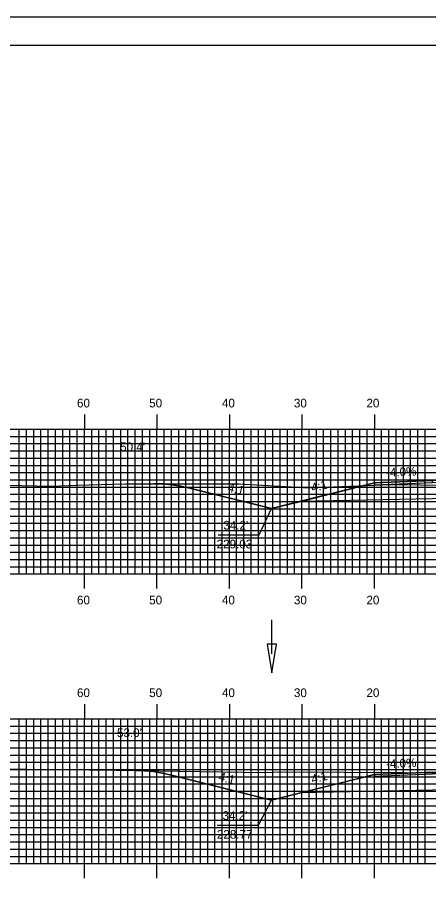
# Model space of a CAD drawing. Extents: x 1803110 to 1803453, y 442591 to 442811.
# Drawn here: x 1803206.4 to 1803263.1, y 442691.2 to 442810.5 of the extents above; entities that cross this region are included whole.
import ezdxf

# ---------------------------------------------------------------- set-up
doc = ezdxf.new("R2010")
doc.units = 0
for name, color, linetype in [('ANNOTATION', 7, 'Continuous'), ('BORDER', 7, 'Continuous'), ('D_Drainage_Ditch_Line', 7, 'Continuous'), ('D_Roadway_Centerline', 7, 'Continuous'), ('D_Roadway_Edge_Shoulder', 7, 'Continuous'), ('D_Roadway_SlopeLines', 7, 'Continuous'), ('D_Roadway_SubGrade', 7, 'Continuous'), ('D_Text_Standard', 7, 'Continuous'), ('H_V ANNOTATION', 7, 'Continuous'), ('MAJOR', 7, 'Continuous'), ('MINOR', 7, 'Continuous'), ('PLOT BOUNDARY', 7, 'Continuous'), ('S_Roadway_Centerline', 7, 'Continuous')]:
    doc.layers.add(name, color=color, linetype=linetype)

msp = doc.modelspace()

# ---------------------------------------------------------------- linework, layer by layer
at = {"layer": 'ANNOTATION'}
for points in [[(1803234.06, 442739.08), (1803239.75, 442739.08), (1803241.45, 442742.69)], [(1803233.95, 442698.98), (1803239.64, 442698.98), (1803241.45, 442702.44)]]:
    msp.add_lwpolyline(points, dxfattribs=at)
at = {"layer": 'BORDER'}
msp.add_lwpolyline([(1803126.03, 442596.67), (1803446.03, 442596.67), (1803446.03, 442806.67), (1803126.03, 442806.67)], close=True, dxfattribs=at)
at = {"layer": 'D_Drainage_Ditch_Line'}
msp.add_line((1803241.48, 442722.65), (1803241.48, 442727.35), dxfattribs=at)
msp.add_lwpolyline([(1803242.14, 442723.96), (1803240.83, 442723.96), (1803241.48, 442720.03)], close=True, dxfattribs=at)
at = {"layer": 'D_Roadway_Centerline'}
for points in [[(1803225.18, 442746.14), (1803226.43, 442746.1), (1803227.68, 442745.98), (1803228.93, 442745.78), (1803230.18, 442745.51), (1803241.45, 442742.69), (1803245.45, 442743.69), (1803255.63, 442746.24), (1803263.63, 442746.56), (1803275.63, 442746.8), (1803287.63, 442746.56), (1803295.63, 442746.24), (1803305.8, 442743.69), (1803309.8, 442742.69), (1803318.11, 442744.77), (1803319.36, 442745.05), (1803320.61, 442745.26), (1803321.86, 442745.4), (1803323.11, 442745.47)], [(1803222.65, 442706.55), (1803223.9, 442706.5), (1803225.15, 442706.37), (1803226.4, 442706.17), (1803227.65, 442705.89), (1803241.45, 442702.44), (1803245.45, 442703.44), (1803255.63, 442705.98), (1803263.63, 442706.3), (1803275.63, 442706.54), (1803287.63, 442706.3), (1803295.63, 442705.98), (1803305.8, 442703.44), (1803309.8, 442702.44), (1803321.68, 442705.41), (1803322.93, 442705.69), (1803324.18, 442705.93), (1803325.43, 442706.11), (1803326.68, 442706.24)]]:
    msp.add_lwpolyline(points, dxfattribs=at)
at = {"layer": 'D_Roadway_Edge_Shoulder'}
for points in [[(1803263.63, 442746.56), (1803255.63, 442746.24), (1803255.63, 442745.99), (1803263.63, 442746.31)], [(1803263.63, 442706.3), (1803255.63, 442705.98), (1803255.63, 442705.73), (1803263.63, 442706.05)]]:
    msp.add_lwpolyline(points, close=True, dxfattribs=at)
at = {"layer": 'D_Roadway_SlopeLines'}
for points in [[(1803241.45, 442742.69), (1803230.18, 442745.51), (1803228.93, 442745.78), (1803227.68, 442745.98), (1803226.43, 442746.1), (1803225.18, 442746.14)], [(1803255.63, 442746.24), (1803241.45, 442742.69)], [(1803241.45, 442702.44), (1803227.65, 442705.89), (1803226.4, 442706.17), (1803225.15, 442706.37), (1803223.9, 442706.5), (1803222.65, 442706.55)], [(1803255.63, 442705.98), (1803241.45, 442702.44)]]:
    msp.add_lwpolyline(points, dxfattribs=at)
at = {"layer": 'D_Roadway_SubGrade'}
for points in [[(1803263.63, 442744.06), (1803245.45, 442743.69), (1803255.63, 442746.24), (1803255.63, 442745.99), (1803263.63, 442746.31), (1803275.63, 442746.55), (1803287.63, 442746.31), (1803295.63, 442745.99), (1803295.63, 442746.24), (1803305.8, 442743.69), (1803287.63, 442744.06), (1803275.63, 442744.3)], [(1803263.63, 442703.8), (1803245.45, 442703.44), (1803255.63, 442705.98), (1803255.63, 442705.73), (1803263.63, 442706.05), (1803275.63, 442706.29), (1803287.63, 442706.05), (1803295.63, 442705.73), (1803295.63, 442705.98), (1803305.8, 442703.44), (1803287.63, 442703.8), (1803275.63, 442704.04)]]:
    msp.add_lwpolyline(points, close=True, dxfattribs=at)
at = {"layer": 'MAJOR'}
for p, q in [((1803215.63, 442755.67), (1803215.63, 442753.67)), ((1803225.63, 442755.67), (1803225.63, 442753.67)), ((1803235.63, 442755.67), (1803235.63, 442753.67)), ((1803245.63, 442755.67), (1803245.63, 442753.67)), ((1803255.63, 442755.67), (1803255.63, 442753.67)), ((1803135.63, 442753.67), (1803415.63, 442753.67)), ((1803135.63, 442753.67), (1803415.63, 442753.67)), ((1803215.63, 442733.67), (1803215.63, 442753.67)), ((1803225.63, 442733.67), (1803225.63, 442753.67)), ((1803235.63, 442733.67), (1803235.63, 442753.67)), ((1803245.63, 442733.67), (1803245.63, 442753.67)), ((1803255.63, 442733.67), (1803255.63, 442753.67)), ((1803135.63, 442748.67), (1803415.63, 442748.67)), ((1803135.63, 442743.67), (1803415.63, 442743.67)), ((1803135.63, 442738.67), (1803415.63, 442738.67)), ((1803135.63, 442733.67), (1803415.63, 442733.67)), ((1803135.63, 442733.67), (1803415.63, 442733.67)), ((1803215.63, 442731.66), (1803215.63, 442733.67)), ((1803225.63, 442731.66), (1803225.63, 442733.67)), ((1803235.63, 442731.66), (1803235.63, 442733.67)), ((1803245.63, 442731.66), (1803245.63, 442733.67)), ((1803255.63, 442731.66), (1803255.63, 442733.67)), ((1803215.63, 442715.67), (1803215.63, 442713.67)), ((1803225.63, 442715.67), (1803225.63, 442713.67)), ((1803235.63, 442715.67), (1803235.63, 442713.67)), ((1803245.63, 442715.67), (1803245.63, 442713.67)), ((1803255.63, 442715.67), (1803255.63, 442713.67)), ((1803135.63, 442713.67), (1803415.63, 442713.67)), ((1803135.63, 442713.67), (1803415.63, 442713.67)), ((1803215.63, 442693.67), (1803215.63, 442713.67)), ((1803225.63, 442693.67), (1803225.63, 442713.67)), ((1803235.63, 442693.67), (1803235.63, 442713.67)), ((1803245.63, 442693.67), (1803245.63, 442713.67)), ((1803255.63, 442693.67), (1803255.63, 442713.67)), ((1803135.63, 442708.67), (1803415.63, 442708.67)), ((1803135.63, 442703.67), (1803415.63, 442703.67)), ((1803135.63, 442698.67), (1803415.63, 442698.67)), ((1803135.63, 442693.67), (1803415.63, 442693.67)), ((1803135.63, 442693.67), (1803415.63, 442693.67)), ((1803215.63, 442691.66), (1803215.63, 442693.67)), ((1803225.63, 442691.66), (1803225.63, 442693.67)), ((1803235.63, 442691.66), (1803235.63, 442693.67)), ((1803245.63, 442691.66), (1803245.63, 442693.67)), ((1803255.63, 442691.66), (1803255.63, 442693.67))]:
    msp.add_line(p, q, dxfattribs=at)
at = {"layer": 'MINOR'}
for p, q in [((1803206.63, 442733.67), (1803206.63, 442753.67)), ((1803207.63, 442733.67), (1803207.63, 442753.67)), ((1803208.63, 442733.67), (1803208.63, 442753.67)), ((1803209.63, 442733.67), (1803209.63, 442753.67)), ((1803210.63, 442733.67), (1803210.63, 442753.67)), ((1803211.63, 442733.67), (1803211.63, 442753.67)), ((1803212.63, 442733.67), (1803212.63, 442753.67)), ((1803213.63, 442733.67), (1803213.63, 442753.67)), ((1803214.63, 442733.67), (1803214.63, 442753.67)), ((1803216.63, 442733.67), (1803216.63, 442753.67)), ((1803217.63, 442733.67), (1803217.63, 442753.67)), ((1803218.63, 442733.67), (1803218.63, 442753.67)), ((1803219.63, 442733.67), (1803219.63, 442753.67)), ((1803220.63, 442733.67), (1803220.63, 442753.67)), ((1803221.63, 442733.67), (1803221.63, 442753.67)), ((1803222.63, 442733.67), (1803222.63, 442753.67)), ((1803223.63, 442733.67), (1803223.63, 442753.67)), ((1803224.63, 442733.67), (1803224.63, 442753.67)), ((1803226.63, 442733.67), (1803226.63, 442753.67)), ((1803227.63, 442733.67), (1803227.63, 442753.67)), ((1803228.63, 442733.67), (1803228.63, 442753.67)), ((1803229.63, 442733.67), (1803229.63, 442753.67)), ((1803230.63, 442733.67), (1803230.63, 442753.67)), ((1803231.63, 442733.67), (1803231.63, 442753.67)), ((1803232.63, 442733.67), (1803232.63, 442753.67)), ((1803233.63, 442733.67), (1803233.63, 442753.67)), ((1803234.63, 442733.67), (1803234.63, 442753.67)), ((1803236.63, 442733.67), (1803236.63, 442753.67)), ((1803237.63, 442733.67), (1803237.63, 442753.67)), ((1803238.63, 442733.67), (1803238.63, 442753.67)), ((1803239.63, 442733.67), (1803239.63, 442753.67)), ((1803240.63, 442733.67), (1803240.63, 442753.67)), ((1803241.63, 442733.67), (1803241.63, 442753.67)), ((1803242.63, 442733.67), (1803242.63, 442753.67)), ((1803243.63, 442733.67), (1803243.63, 442753.67)), ((1803244.63, 442733.67), (1803244.63, 442753.67)), ((1803246.63, 442733.67), (1803246.63, 442753.67)), ((1803247.63, 442733.67), (1803247.63, 442753.67)), ((1803248.63, 442733.67), (1803248.63, 442753.67)), ((1803249.63, 442733.67), (1803249.63, 442753.67)), ((1803250.63, 442733.67), (1803250.63, 442753.67)), ((1803251.63, 442733.67), (1803251.63, 442753.67)), ((1803252.63, 442733.67), (1803252.63, 442753.67)), ((1803253.63, 442733.67), (1803253.63, 442753.67)), ((1803254.63, 442733.67), (1803254.63, 442753.67)), ((1803256.63, 442733.67), (1803256.63, 442753.67)), ((1803257.63, 442733.67), (1803257.63, 442753.67)), ((1803258.63, 442733.67), (1803258.63, 442753.67)), ((1803259.63, 442733.67), (1803259.63, 442753.67)), ((1803260.63, 442733.67), (1803260.63, 442753.67)), ((1803261.63, 442733.67), (1803261.63, 442753.67)), ((1803262.63, 442733.67), (1803262.63, 442753.67)), ((1803135.63, 442752.67), (1803415.63, 442752.67)), ((1803135.63, 442751.67), (1803415.63, 442751.67)), ((1803135.63, 442750.67), (1803415.63, 442750.67)), ((1803135.63, 442749.67), (1803415.63, 442749.67)), ((1803135.63, 442747.67), (1803415.63, 442747.67)), ((1803135.63, 442746.67), (1803415.63, 442746.67)), ((1803135.63, 442745.67), (1803415.63, 442745.67)), ((1803135.63, 442744.67), (1803415.63, 442744.67)), ((1803135.63, 442742.67), (1803415.63, 442742.67)), ((1803135.63, 442741.67), (1803415.63, 442741.67)), ((1803135.63, 442740.67), (1803415.63, 442740.67)), ((1803135.63, 442739.67), (1803415.63, 442739.67)), ((1803135.63, 442737.67), (1803415.63, 442737.67)), ((1803135.63, 442736.67), (1803415.63, 442736.67)), ((1803135.63, 442735.67), (1803415.63, 442735.67)), ((1803135.63, 442734.67), (1803415.63, 442734.67)), ((1803206.63, 442693.67), (1803206.63, 442713.67)), ((1803207.63, 442693.67), (1803207.63, 442713.67)), ((1803208.63, 442693.67), (1803208.63, 442713.67)), ((1803209.63, 442693.67), (1803209.63, 442713.67)), ((1803210.63, 442693.67), (1803210.63, 442713.67)), ((1803211.63, 442693.67), (1803211.63, 442713.67)), ((1803212.63, 442693.67), (1803212.63, 442713.67)), ((1803213.63, 442693.67), (1803213.63, 442713.67)), ((1803214.63, 442693.67), (1803214.63, 442713.67)), ((1803216.63, 442693.67), (1803216.63, 442713.67)), ((1803217.63, 442693.67), (1803217.63, 442713.67)), ((1803218.63, 442693.67), (1803218.63, 442713.67)), ((1803219.63, 442693.67), (1803219.63, 442713.67)), ((1803220.63, 442693.67), (1803220.63, 442713.67)), ((1803221.63, 442693.67), (1803221.63, 442713.67)), ((1803222.63, 442693.67), (1803222.63, 442713.67)), ((1803223.63, 442693.67), (1803223.63, 442713.67)), ((1803224.63, 442693.67), (1803224.63, 442713.67)), ((1803226.63, 442693.67), (1803226.63, 442713.67)), ((1803227.63, 442693.67), (1803227.63, 442713.67)), ((1803228.63, 442693.67), (1803228.63, 442713.67)), ((1803229.63, 442693.67), (1803229.63, 442713.67)), ((1803230.63, 442693.67), (1803230.63, 442713.67)), ((1803231.63, 442693.67), (1803231.63, 442713.67)), ((1803232.63, 442693.67), (1803232.63, 442713.67)), ((1803233.63, 442693.67), (1803233.63, 442713.67)), ((1803234.63, 442693.67), (1803234.63, 442713.67)), ((1803236.63, 442693.67), (1803236.63, 442713.67)), ((1803237.63, 442693.67), (1803237.63, 442713.67)), ((1803238.63, 442693.67), (1803238.63, 442713.67)), ((1803239.63, 442693.67), (1803239.63, 442713.67)), ((1803240.63, 442693.67), (1803240.63, 442713.67)), ((1803241.63, 442693.67), (1803241.63, 442713.67)), ((1803242.63, 442693.67), (1803242.63, 442713.67)), ((1803243.63, 442693.67), (1803243.63, 442713.67)), ((1803244.63, 442693.67), (1803244.63, 442713.67)), ((1803246.63, 442693.67), (1803246.63, 442713.67)), ((1803247.63, 442693.67), (1803247.63, 442713.67)), ((1803248.63, 442693.67), (1803248.63, 442713.67)), ((1803249.63, 442693.67), (1803249.63, 442713.67)), ((1803250.63, 442693.67), (1803250.63, 442713.67)), ((1803251.63, 442693.67), (1803251.63, 442713.67)), ((1803252.63, 442693.67), (1803252.63, 442713.67)), ((1803253.63, 442693.67), (1803253.63, 442713.67)), ((1803254.63, 442693.67), (1803254.63, 442713.67)), ((1803256.63, 442693.67), (1803256.63, 442713.67)), ((1803257.63, 442693.67), (1803257.63, 442713.67)), ((1803258.63, 442693.67), (1803258.63, 442713.67)), ((1803259.63, 442693.67), (1803259.63, 442713.67)), ((1803260.63, 442693.67), (1803260.63, 442713.67)), ((1803261.63, 442693.67), (1803261.63, 442713.67)), ((1803262.63, 442693.67), (1803262.63, 442713.67)), ((1803135.63, 442712.67), (1803415.63, 442712.67)), ((1803135.63, 442711.67), (1803415.63, 442711.67)), ((1803135.63, 442710.67), (1803415.63, 442710.67)), ((1803135.63, 442709.67), (1803415.63, 442709.67)), ((1803135.63, 442707.67), (1803415.63, 442707.67)), ((1803135.63, 442706.67), (1803415.63, 442706.67)), ((1803135.63, 442705.67), (1803415.63, 442705.67)), ((1803135.63, 442704.67), (1803415.63, 442704.67)), ((1803135.63, 442702.67), (1803415.63, 442702.67)), ((1803135.63, 442701.67), (1803415.63, 442701.67)), ((1803135.63, 442700.67), (1803415.63, 442700.67)), ((1803135.63, 442699.67), (1803415.63, 442699.67)), ((1803135.63, 442697.67), (1803415.63, 442697.67)), ((1803135.63, 442696.67), (1803415.63, 442696.67)), ((1803135.63, 442695.67), (1803415.63, 442695.67)), ((1803135.63, 442694.67), (1803415.63, 442694.67))]:
    msp.add_line(p, q, dxfattribs=at)
at = {"layer": 'PLOT BOUNDARY'}
msp.add_lwpolyline([(1803109.84, 442590.55), (1803449.84, 442590.55), (1803449.84, 442810.55), (1803109.84, 442810.55)], close=True, dxfattribs=at)
at = {"layer": 'S_Roadway_Centerline'}
for points in [[(1803194.07, 442746.15), (1803207, 442745.88), (1803211.04, 442745.81), (1803214.63, 442745.92), (1803221.3, 442746.14), (1803233.87, 442746.13), (1803236.99, 442746.1), (1803246.61, 442745.55), (1803256.81, 442745.97), (1803259.64, 442746.04), (1803268.87, 442745.82)], [(1803193.28, 442706.83), (1803212.45, 442706.67), (1803216.28, 442706.64), (1803216.67, 442706.64), (1803217.04, 442706.64), (1803237.6, 442706.32), (1803240.09, 442706.27), (1803243.18, 442706.33), (1803259.7, 442706.27), (1803263.02, 442706.23), (1803267.02, 442706.24)]]:
    msp.add_lwpolyline(points, dxfattribs=at)

# ---------------------------------------------------------------- texts
at = {"layer": 'ANNOTATION'}
for s, rotation, p in [('-4.0%', 2.2906, (1803257.26, 442747.1)), ('4:1', 345.9638, (1803235.32, 442745.09)), ('4:1', 14.0362, (1803247.08, 442744.96)), ('-4.0%', 2.2906, (1803257.26, 442706.85)), ('4:1', 345.9638, (1803234.06, 442705.15)), ('4:1', 14.0362, (1803247.08, 442704.71))]:
    msp.add_text(s, height=1.2, rotation=rotation, dxfattribs=at).set_placement(p)
for s, p in [("34.2'", (1803234.79, 442739.8)), ('229.03', (1803233.87, 442737.2)), ("34.2'", (1803234.68, 442699.71)), ('228.77', (1803233.9, 442697.11))]:
    msp.add_text(s, height=1.2, dxfattribs=at).set_placement(p)
at = {"layer": 'D_Text_Standard'}
for s, p in [("50.4'", (1803220.55, 442750.63)), ("53.0'", (1803220.12, 442711.15))]:
    msp.add_text(s, height=1.2, dxfattribs=at).set_placement(p)
at = {"layer": 'H_V ANNOTATION'}
for s, p in [('60', (1803214.6, 442756.67)), ('50', (1803224.56, 442756.67)), ('40', (1803234.6, 442756.67)), ('30', (1803244.53, 442756.67)), ('20', (1803254.54, 442756.67)), ('60', (1803214.6, 442729.47)), ('50', (1803224.56, 442729.47)), ('40', (1803234.6, 442729.47)), ('30', (1803244.53, 442729.47)), ('20', (1803254.54, 442729.47)), ('60', (1803214.6, 442716.67)), ('50', (1803224.56, 442716.67)), ('40', (1803234.6, 442716.67)), ('30', (1803244.53, 442716.67)), ('20', (1803254.54, 442716.67))]:
    msp.add_text(s, height=1.2, dxfattribs=at).set_placement(p)

doc.saveas('drawing.dxf')
